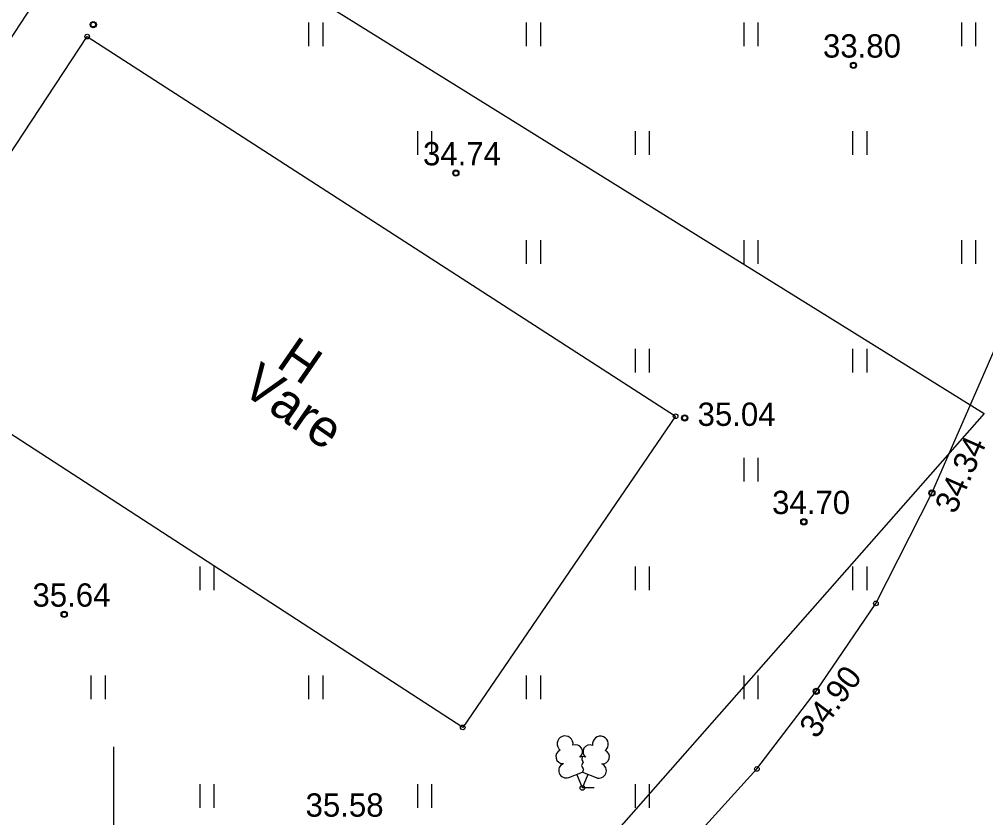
# Model space of a CAD drawing. Extents: x 641898 to 642452, y 6471715 to 6472255.
# Drawn here: x 641996.97 to 642028.05, y 6472150.22 to 6472175.9 of the extents above; entities that cross this region are included whole.
import ezdxf

# ---------------------------------------------------------------- set-up
doc = ezdxf.new("R2010")
doc.units = 0
for name, color, linetype in [('HALJASTUS', 7, 'Continuous'), ('HOONE', 7, 'Continuous'), ('KORGUS-EH2000', 7, 'Continuous'), ('MOOTMPUNKT', 7, 'Continuous'), ('PIIR', 7, 'Continuous'), ('PUU', 7, 'Continuous'), ('TEE', 7, 'Continuous'), ('VORK', 7, 'Continuous')]:
    doc.layers.add(name, color=color, linetype=linetype)

msp = doc.modelspace()

# ---------------------------------------------------------------- linework, layer by layer
at = {"layer": 'HALJASTUS'}
for p, q in [((642006.275, 6472175.795), (642006.275, 6472175.034)), ((642006.73, 6472175.795), (642006.73, 6472175.034)), ((642013.275, 6472175.795), (642013.275, 6472175.034)), ((642013.73, 6472175.795), (642013.73, 6472175.034)), ((642020.275, 6472175.795), (642020.275, 6472175.034)), ((642020.73, 6472175.795), (642020.73, 6472175.034)), ((642027.275, 6472175.795), (642027.275, 6472175.034)), ((642027.73, 6472175.795), (642027.73, 6472175.034)), ((642009.775, 6472172.295), (642009.775, 6472171.534)), ((642010.23, 6472172.295), (642010.23, 6472171.534)), ((642016.775, 6472172.295), (642016.775, 6472171.534)), ((642017.23, 6472172.295), (642017.23, 6472171.534)), ((642023.775, 6472172.295), (642023.775, 6472171.534)), ((642024.23, 6472172.295), (642024.23, 6472171.534)), ((642013.275, 6472168.795), (642013.275, 6472168.034)), ((642013.73, 6472168.795), (642013.73, 6472168.034)), ((642020.275, 6472168.795), (642020.275, 6472168.034)), ((642020.73, 6472168.795), (642020.73, 6472168.034)), ((642027.275, 6472168.795), (642027.275, 6472168.034)), ((642027.73, 6472168.795), (642027.73, 6472168.034)), ((642016.775, 6472165.295), (642016.775, 6472164.534)), ((642017.23, 6472165.295), (642017.23, 6472164.534)), ((642023.775, 6472165.295), (642023.775, 6472164.534)), ((642024.23, 6472165.295), (642024.23, 6472164.534)), ((642020.275, 6472161.795), (642020.275, 6472161.034)), ((642020.73, 6472161.795), (642020.73, 6472161.034)), ((642002.775, 6472158.295), (642002.775, 6472157.534)), ((642003.23, 6472158.295), (642003.23, 6472157.534)), ((642016.775, 6472158.295), (642016.775, 6472157.534)), ((642017.23, 6472158.295), (642017.23, 6472157.534)), ((642023.775, 6472158.295), (642023.775, 6472157.534)), ((642024.23, 6472158.295), (642024.23, 6472157.534)), ((641999.275, 6472154.795), (641999.275, 6472154.034)), ((641999.73, 6472154.795), (641999.73, 6472154.034)), ((642006.275, 6472154.795), (642006.275, 6472154.034)), ((642006.73, 6472154.795), (642006.73, 6472154.034)), ((642013.275, 6472154.795), (642013.275, 6472154.034)), ((642013.73, 6472154.795), (642013.73, 6472154.034)), ((642020.275, 6472154.795), (642020.275, 6472154.034)), ((642020.73, 6472154.795), (642020.73, 6472154.034)), ((642002.775, 6472151.295), (642002.775, 6472150.534)), ((642003.23, 6472151.295), (642003.23, 6472150.534)), ((642009.775, 6472151.295), (642009.775, 6472150.534)), ((642010.23, 6472151.295), (642010.23, 6472150.534)), ((642016.775, 6472151.295), (642016.775, 6472150.534)), ((642017.23, 6472151.295), (642017.23, 6472150.534))]:
    msp.add_line(p, q, dxfattribs=at)
at = {"layer": 'HOONE'}
msp.add_lwpolyline([(641999.152, 6472175.34), (642018.08, 6472163.129), (642011.231, 6472153.121), (641992.517, 6472165.267), (641999.152, 6472175.34)], dxfattribs=at)
at = {"layer": 'KORGUS-EH2000'}
for centre in [(641999.347, 6472175.726), (642023.801, 6472174.415), (642011.012, 6472170.95), (642018.372, 6472163.076), (642026.323, 6472160.658), (642022.204, 6472159.733), (641998.413, 6472156.755), (642022.603, 6472154.282)]:
    msp.add_circle(centre, 0.1, dxfattribs=at)
at = {"layer": 'MOOTMPUNKT'}
for centre in [(641999.347, 6472175.726), (641999.152, 6472175.34), (642023.801, 6472174.415), (642011.012, 6472170.95), (642018.08, 6472163.129), (642018.372, 6472163.076), (642026.323, 6472160.658), (642022.204, 6472159.733), (642024.521, 6472157.111), (641998.413, 6472156.755), (642022.603, 6472154.282), (642011.231, 6472153.121), (642020.695, 6472151.784), (642015.082, 6472151.177)]:
    msp.add_circle(centre, 0.075, dxfattribs=at)
at = {"layer": 'PIIR'}
for p, q in [((642000.12, 6472180.55), (641967.79, 6472130.98)), ((642000.12, 6472180.55), (642028, 6472163.22)), ((642028, 6472163.22), (641981.64, 6472110.54))]:
    msp.add_line(p, q, dxfattribs=at)
at = {"layer": 'PUU'}
for p, q in [((642014.642, 6472151.512), (642015.087, 6472151.687)), ((642015.082, 6472151.177), (642014.907, 6472151.617)), ((642015.082, 6472151.177), (642015.262, 6472151.617)), ((642015.087, 6472151.687), (642015.527, 6472151.507)), ((642015.462, 6472151.177), (642015.082, 6472151.177))]:
    msp.add_line(p, q, dxfattribs=at)
msp.add_lwpolyline([(642015.087, 6472152.182), (642015.067, 6472152.107), (642015.067, 6472152.087), (642015.077, 6472152.057), (642015.097, 6472152.022), (642015.102, 6472152.002), (642015.087, 6472151.967), (642015.062, 6472151.917), (642015.057, 6472151.892), (642015.062, 6472151.877), (642015.072, 6472151.847), (642015.107, 6472151.787), (642015.112, 6472151.767), (642015.107, 6472151.747), (642015.092, 6472151.712), (642015.087, 6472151.687)], dxfattribs=at)
for centre, radius, start, end in [((642014.525, 6472152.591), 0.256, 350.4856, 111.5002), ((642014.525, 6472152.591), 0.256, 111.5027, 232.5173), ((642014.86, 6472152.341), 0.224, 308.5041, 111.5725), ((642015.323, 6472152.336), 0.225, 67.7016, 230.5126), ((642015.661, 6472152.582), 0.256, 67.6168, 188.6314), ((642015.661, 6472152.582), 0.256, 306.5997, 67.6143), ((642014.451, 6472152.18), 0.224, 111.4304, 274.4987), ((642015.728, 6472152.17), 0.224, 264.6183, 67.6866), ((642014.556, 6472151.735), 0.237, 111.5014, 291.5004), ((642015.086, 6472151.944), 0.237, 66.7655, 111.5015), ((642015.617, 6472151.727), 0.237, 247.6166, 67.6155)]:
    msp.add_arc(centre, radius, start, end, dxfattribs=at)
at = {"layer": 'TEE'}
msp.add_lwpolyline([(642017.912, 6472148.72), (642020.695, 6472151.784), (642022.603, 6472154.282), (642024.521, 6472157.111), (642026.323, 6472160.658), (642029.336, 6472167.548), (642033.234, 6472174.177), (642034.475, 6472175.561), (642035.243, 6472175.522), (642035.264, 6472175.53), (642036.109, 6472174.698), (642037.079, 6472174.127), (642036.986, 6472172.928), (642034.73, 6472165.952), (642032.609, 6472158.907), (642033.633, 6472158.354), (642037.133, 6472156.479), (642037.163, 6472156.461), (642037.166, 6472155.768), (642048.88, 6472149.179)], dxfattribs=at)
at = {"layer": 'VORK'}
msp.add_line((642000, 6472152.5), (642000, 6472147.5), dxfattribs=at)

# ---------------------------------------------------------------- texts
at = {"layer": 'HOONE'}
for s, p in [('H', (642005.193, 6472164.753)), ('Vare', (642004.052, 6472163.926))]:
    msp.add_text(s, height=1.2, rotation=325.3929, dxfattribs=at).set_placement(p)
at = {"layer": 'KORGUS-EH2000'}
for s, p in [('33.80', (642022.819, 6472174.665)), ('34.74', (642009.954, 6472171.2)), ('35.04', (642018.786, 6472162.819)), ('34.70', (642021.184, 6472159.983)), ('35.64', (641997.392, 6472157.005)), ('35.58', (642006.177, 6472150.25))]:
    msp.add_text(s, height=0.75, dxfattribs=at).set_placement(p)
for s, rotation, p in [('34.34', 66.1913, (642027.075, 6472159.955)), ('34.90', 53.1002, (642022.604, 6472152.726))]:
    msp.add_text(s, height=0.75, rotation=rotation, dxfattribs=at).set_placement(p)

doc.saveas('drawing.dxf')
